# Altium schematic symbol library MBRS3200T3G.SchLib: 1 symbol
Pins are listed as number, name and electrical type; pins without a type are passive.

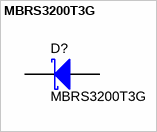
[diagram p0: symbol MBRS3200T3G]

## MBRS3200T3G
designator D?
DIODE SCHOTTKY 3A 200V SMB; Manufacturer: ON Semiconductor; Alternate Manufacturer: Any; Alternate PartNumber: Equivalent; U/M: EA; Vf_V: 0.43; Io_A: 3; Vr_V: 200; Value: 0.43V
signal-integrity model Diode
simulation model MBRS2040LT3
footprint SMB
pins: 1 K, 2 A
